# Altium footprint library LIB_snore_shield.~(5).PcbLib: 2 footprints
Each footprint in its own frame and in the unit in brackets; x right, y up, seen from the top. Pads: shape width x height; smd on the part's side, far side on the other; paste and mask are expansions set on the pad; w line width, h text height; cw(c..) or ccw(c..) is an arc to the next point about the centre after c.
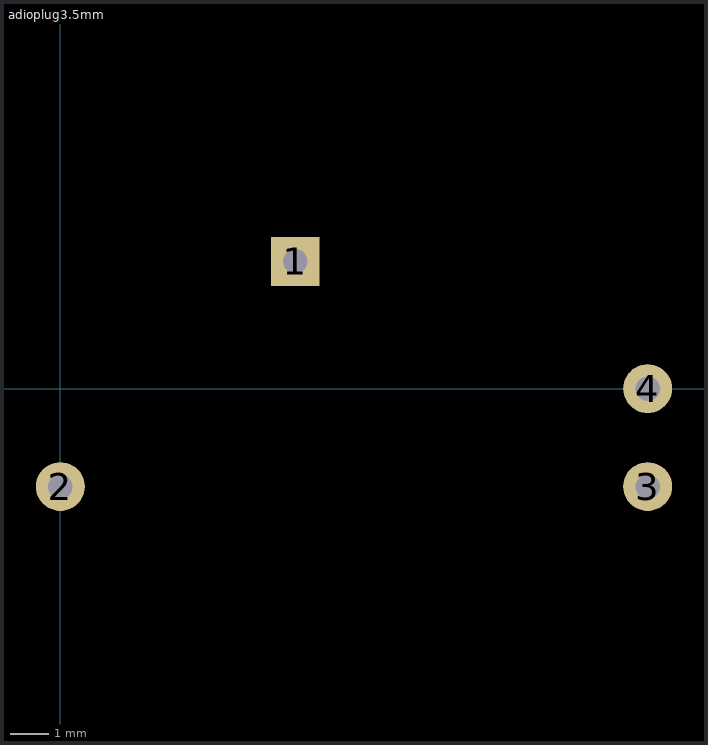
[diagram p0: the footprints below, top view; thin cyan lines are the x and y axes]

## adioplug3.5mm [mil]
pads (4):
  rect 50x50 / inner rect 100x50 / far side rect 50x50 hole 25: 1(240,130)
  round 50 / inner oval 100x50 / far side round 50 hole 25: 2(0,-100) 3(600,-100) 4(600,0)

## PCBComponent_1 [mil]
